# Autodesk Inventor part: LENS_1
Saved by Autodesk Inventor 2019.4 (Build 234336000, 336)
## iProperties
Created: 2020-05
Part Number: LENS_1
Material: Generic
Document SubType Name: Modeling
Designer: Administrator
Density: 1 g/cm^3
Appearance: Default
Title: LENS_1
Author: Administrator
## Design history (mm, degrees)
feature "Body1"
body "Solid1"
